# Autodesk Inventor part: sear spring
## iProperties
Created: 2006-04
Part Number: sear spring
Document SubType Name: Modeling
Designer: Калинин
Author: Калинин
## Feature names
1. Пружина1
2. Выдавливание1 [Extrusion]
3. Сдвиг1
4. Выдавливание2 [Extrusion]
5. Вращение1 [Revolution]
6. Выдавливание3 [Extrusion]
